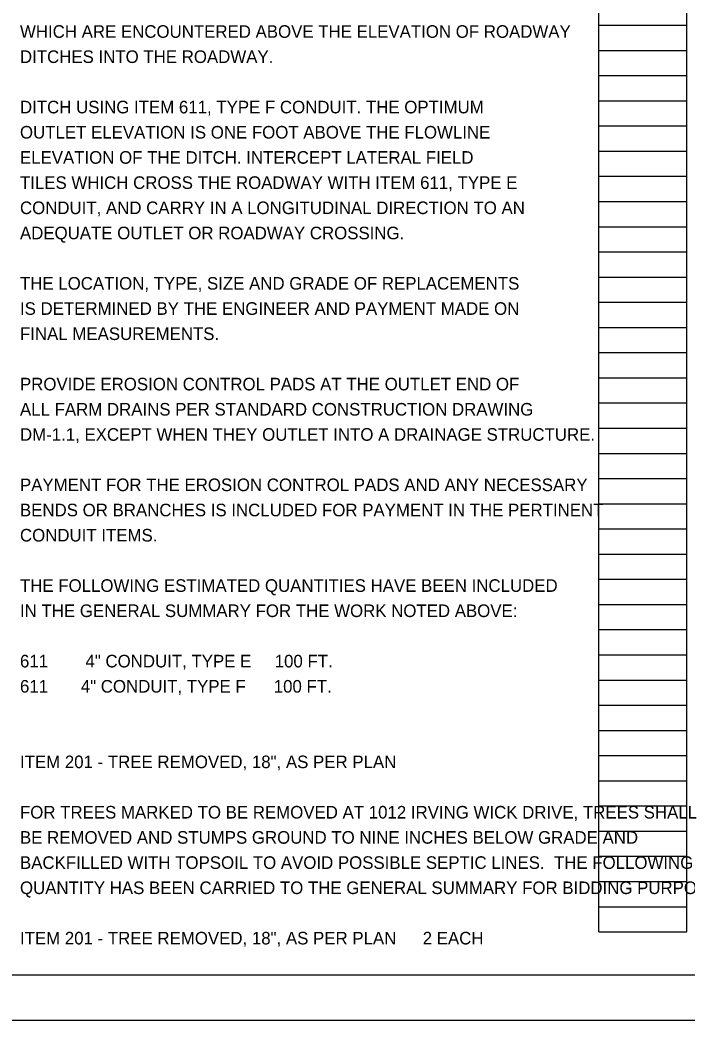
# Model space of a CAD drawing. Extents: x 0 to 36.9, y 0 to 22.
# Drawn here: x 17.24 to 24.66, y 0 to 11.12 of the extents above; entities that cross this region are included whole.
import ezdxf

# ---------------------------------------------------------------- set-up
doc = ezdxf.new("R2010")
doc.units = 0
for name, color, linetype in [('SH_Border', 7, 'Continuous'), ('SH_Cut_Line', 7, 'Continuous'), ('SH_Data', 7, 'Continuous'), ('SH_Text', 7, 'Continuous')]:
    doc.layers.add(name, color=color, linetype=linetype)

msp = doc.modelspace()

# ---------------------------------------------------------------- linework, layer by layer
at = {"layer": 'SH_Border'}
msp.add_lwpolyline([(1.5, 21.5), (33.5, 21.5), (33.5, 0.5), (1.5, 0.5)], close=True, dxfattribs=at)
at = {"layer": 'SH_Cut_Line'}
msp.add_lwpolyline([(0, 0), (34, 0), (34, 22), (0, 22)], close=True, dxfattribs=at)
at = {"layer": 'SH_Data'}
for p, q in [((23.68, 0.98), (23.68, 21.14)), ((24.66, 0.98), (24.66, 21.14)), ((23.68, 11.06), (24.66, 11.06)), ((23.68, 10.78), (24.66, 10.78)), ((23.68, 10.5), (24.66, 10.5)), ((23.68, 10.22), (24.66, 10.22)), ((23.68, 9.94), (24.66, 9.94)), ((23.68, 9.66), (24.66, 9.66)), ((23.68, 9.38), (24.66, 9.38)), ((23.68, 9.1), (24.66, 9.1)), ((23.68, 8.82), (24.66, 8.82)), ((23.68, 8.54), (24.66, 8.54)), ((23.68, 8.26), (24.66, 8.26)), ((23.68, 7.98), (24.66, 7.98)), ((23.68, 7.7), (24.66, 7.7)), ((23.68, 7.42), (24.66, 7.42)), ((23.68, 7.14), (24.66, 7.14)), ((23.68, 6.86), (24.66, 6.86)), ((23.68, 6.58), (24.66, 6.58)), ((23.68, 6.3), (24.66, 6.3)), ((23.68, 6.02), (24.66, 6.02)), ((23.68, 5.74), (24.66, 5.74)), ((23.68, 5.46), (24.66, 5.46)), ((23.68, 5.18), (24.66, 5.18)), ((23.68, 4.9), (24.66, 4.9)), ((23.68, 4.62), (24.66, 4.62)), ((23.68, 4.34), (24.66, 4.34)), ((23.68, 4.06), (24.66, 4.06)), ((23.68, 3.78), (24.66, 3.78)), ((23.68, 3.5), (24.66, 3.5)), ((23.68, 3.22), (24.66, 3.22)), ((23.68, 2.94), (24.66, 2.94)), ((23.68, 2.66), (24.66, 2.66)), ((23.68, 2.38), (24.66, 2.38)), ((23.68, 2.1), (24.66, 2.1)), ((23.68, 1.82), (24.66, 1.82)), ((23.68, 1.54), (24.66, 1.54)), ((23.68, 1.26), (24.66, 1.26)), ((23.68, 0.98), (24.66, 0.98))]:
    msp.add_line(p, q, dxfattribs=at)

# ---------------------------------------------------------------- texts
at = {"layer": 'SH_Text'}
for s, p in [('WHICH ARE ENCOUNTERED ABOVE THE ELEVATION OF ROADWAY', (17.24, 10.92)), ('DITCHES INTO THE ROADWAY.', (17.24, 10.64)), ('DITCH USING ITEM 611, TYPE F CONDUIT. THE OPTIMUM', (17.24, 10.08)), ('OUTLET ELEVATION IS ONE FOOT ABOVE THE FLOWLINE', (17.24, 9.8)), ('ELEVATION OF THE DITCH. INTERCEPT LATERAL FIELD', (17.24, 9.52)), ('TILES WHICH CROSS THE ROADWAY WITH ITEM 611, TYPE E', (17.24, 9.24)), ('CONDUIT, AND CARRY IN A LONGITUDINAL DIRECTION TO AN', (17.24, 8.96)), ('ADEQUATE OUTLET OR ROADWAY CROSSING.', (17.24, 8.68)), ('THE LOCATION, TYPE, SIZE AND GRADE OF REPLACEMENTS', (17.24, 8.12)), ('IS DETERMINED BY THE ENGINEER AND PAYMENT MADE ON', (17.24, 7.84)), ('FINAL MEASUREMENTS.', (17.24, 7.56)), ('PROVIDE EROSION CONTROL PADS AT THE OUTLET END OF', (17.24, 7)), ('ALL FARM DRAINS PER STANDARD CONSTRUCTION DRAWING', (17.24, 6.72)), ('DM-1.1, EXCEPT WHEN THEY OUTLET INTO A DRAINAGE STRUCTURE.', (17.24, 6.44)), ('PAYMENT FOR THE EROSION CONTROL PADS AND ANY NECESSARY', (17.24, 5.88)), ('BENDS OR BRANCHES IS INCLUDED FOR PAYMENT IN THE PERTINENT', (17.24, 5.6)), ('CONDUIT ITEMS.', (17.24, 5.32)), ('THE FOLLOWING ESTIMATED QUANTITIES HAVE BEEN INCLUDED', (17.24, 4.76)), ('IN THE GENERAL SUMMARY FOR THE WORK NOTED ABOVE:', (17.24, 4.48)), ('611        4" CONDUIT, TYPE E     100 FT.', (17.24, 3.92)), ('611       4" CONDUIT, TYPE F      100 FT.', (17.24, 3.64)), ('ITEM 201 - TREE REMOVED, 18", AS PER PLAN', (17.24, 2.8)), ('FOR TREES MARKED TO BE REMOVED AT 1012 IRVING WICK DRIVE, TREES SHALL', (17.24, 2.24)), ('BE REMOVED AND STUMPS GROUND TO NINE INCHES BELOW GRADE AND ', (17.24, 1.96)), ('BACKFILLED WITH TOPSOIL TO AVOID POSSIBLE SEPTIC LINES.  THE FOLLOWING', (17.24, 1.68)), ('QUANTITY HAS BEEN CARRIED TO THE GENERAL SUMMARY FOR BIDDING PURPOSES.', (17.24, 1.4)), ('ITEM 201 - TREE REMOVED, 18", AS PER PLAN', (17.24, 0.84)), ('2 EACH', (21.72, 0.84))]:
    msp.add_text(s, height=0.14, dxfattribs=at).set_placement(p)

doc.saveas('drawing.dxf')
